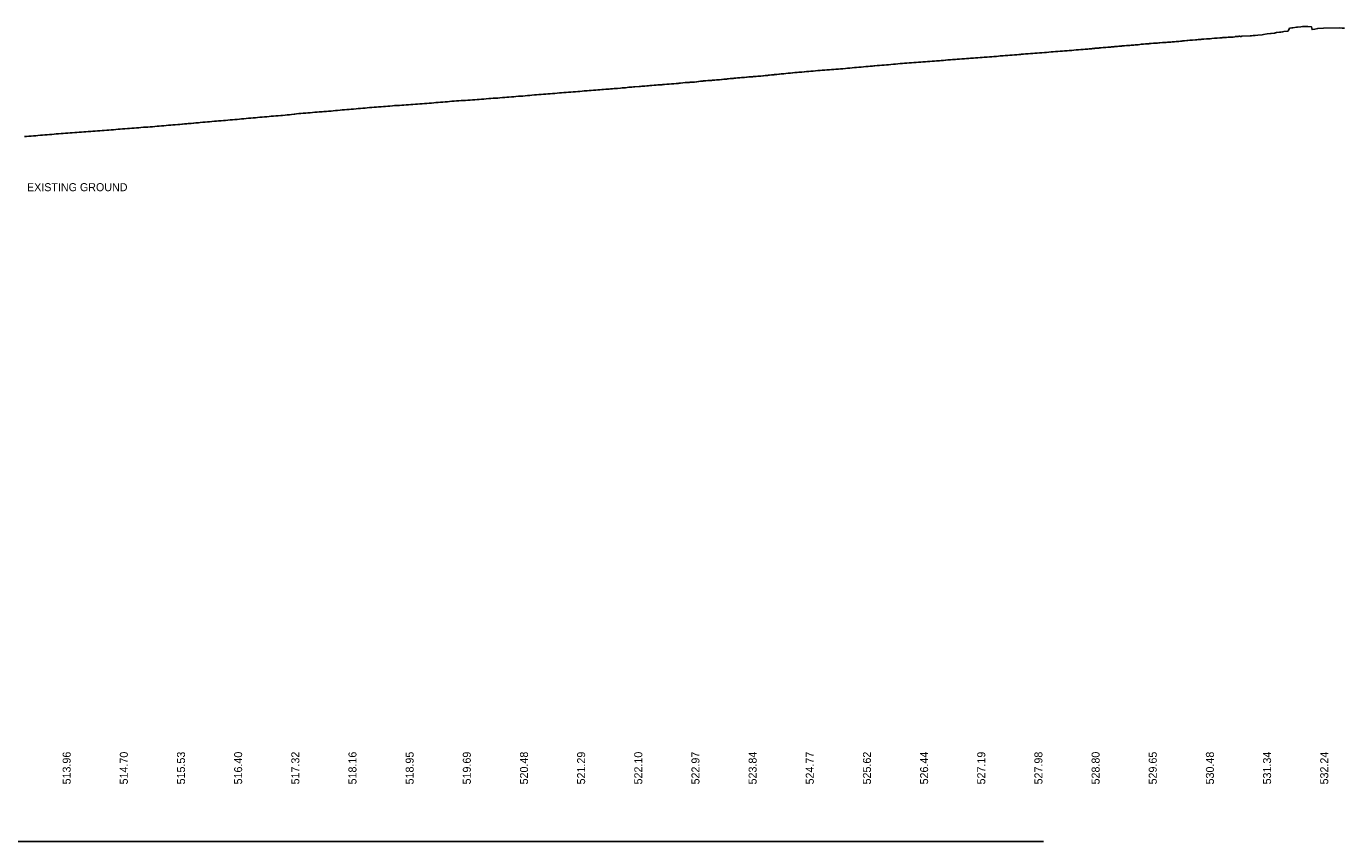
# Model space of a CAD drawing. Extents: x 2017200 to 2047700, y 854850 to 893350.
# Drawn here: x 2021610 to 2022763, y 886100 to 886813 of the extents above; entities that cross this region are included whole.
import ezdxf

# ---------------------------------------------------------------- set-up
doc = ezdxf.new("R2010")
doc.units = 0
for name, color, linetype in [('RD_DDB_Profile_EX', 7, 'Continuous'), ('RD_DDB_Profile_Lbl', 7, 'Continuous'), ('RD_DDB_StripGrade', 7, 'Continuous'), ('RD_GPK_Profile_Cell', 7, 'Continuous')]:
    doc.layers.add(name, color=color, linetype=linetype)

msp = doc.modelspace()

# ---------------------------------------------------------------- linework, layer by layer
at = {"layer": 'RD_DDB_Profile_EX'}
msp.add_lwpolyline([(2021608.5, 886716.4), (2021610.4, 886716.6), (2021612.5, 886716.7), (2021614.5, 886716.9), (2021616.4, 886717), (2021618.5, 886717.2), (2021620.4, 886717.4), (2021622.5, 886717.6), (2021624.5, 886717.7), (2021626.5, 886717.9), (2021628.5, 886718.1), (2021630.5, 886718.3), (2021632.4, 886718.4), (2021634.5, 886718.6), (2021636.4, 886718.7), (2021638.5, 886718.9), (2021640.6, 886719), (2021642.4, 886719.2), (2021644.5, 886719.4), (2021646.5, 886719.5), (2021648.5, 886719.7), (2021650.4, 886719.8), (2021652.5, 886720), (2021654.5, 886720.1), (2021656.4, 886720.2), (2021658.4, 886720.4), (2021660.4, 886720.6), (2021662.4, 886720.7), (2021664.4, 886720.8), (2021666.5, 886720.9), (2021668.4, 886721.1), (2021670.5, 886721.2), (2021672.4, 886721.4), (2021674.5, 886721.5), (2021676.5, 886721.7), (2021678.4, 886721.8), (2021680.5, 886722), (2021682.5, 886722), (2021684.5, 886722.2), (2021686.5, 886722.4), (2021688.5, 886722.5), (2021690.4, 886722.8), (2021692.4, 886722.9), (2021694.4, 886723.1), (2021696.5, 886723.2), (2021698.6, 886723.4), (2021700.5, 886723.6), (2021702.6, 886723.8), (2021704.4, 886723.9), (2021706.5, 886724.1), (2021708.5, 886724.2), (2021710.5, 886724.4), (2021712.7, 886724.6), (2021714.4, 886724.7), (2021716.4, 886724.8), (2021718.5, 886725), (2021720.7, 886725.1), (2021722.5, 886725.3), (2021724.6, 886725.5), (2021726.4, 886725.6), (2021728.5, 886725.8), (2021730.5, 886725.9), (2021732.5, 886726.1), (2021734.5, 886726.3), (2021734.8, 886726.3), (2021736.6, 886726.5), (2021738.4, 886726.7), (2021738.7, 886726.7), (2021740.5, 886726.8), (2021742.7, 886727), (2021744.1, 886727.1), (2021744.5, 886727.1), (2021746.3, 886727.3), (2021746.7, 886727.3), (2021748.5, 886727.5), (2021749.1, 886727.5), (2021750.5, 886727.7), (2021751.9, 886727.8), (2021752.4, 886727.8), (2021754.2, 886728), (2021754.5, 886728), (2021756.5, 886728.2), (2021756.8, 886728.2), (2021758.5, 886728.4), (2021760.3, 886728.5), (2021760.7, 886728.6), (2021762.4, 886728.7), (2021764.6, 886728.9), (2021766.1, 886729), (2021766.5, 886729.1), (2021768.6, 886729.3), (2021770.5, 886729.4), (2021772.5, 886729.6), (2021774.7, 886729.8), (2021776.5, 886730), (2021778.4, 886730.1), (2021780.5, 886730.3), (2021782.6, 886730.5), (2021784.5, 886730.6), (2021786.6, 886730.8), (2021788.4, 886731), (2021790.5, 886731.2), (2021792.5, 886731.3), (2021794.5, 886731.5), (2021796.7, 886731.7), (2021798.4, 886731.9), (2021800.6, 886732), (2021802.5, 886732.2), (2021804.5, 886732.4), (2021806.5, 886732.5), (2021808.5, 886732.7), (2021810.6, 886732.9), (2021812.5, 886733.1), (2021814.4, 886733.3), (2021816.5, 886733.4), (2021818.6, 886733.6), (2021820.5, 886733.7), (2021822.6, 886734), (2021824.4, 886734.2), (2021826.5, 886734.4), (2021828.5, 886734.5), (2021830.5, 886734.7), (2021832.7, 886734.9), (2021834.4, 886735), (2021836.5, 886735.2), (2021838.4, 886735.5), (2021840.3, 886735.6), (2021842.3, 886735.8), (2021844.5, 886736), (2021845.1, 886736.1), (2021846.4, 886736.3), (2021848.5, 886736.5), (2021850.4, 886736.6), (2021852.5, 886736.8), (2021854.6, 886737), (2021856.5, 886737.2), (2021858.6, 886737.3), (2021860.4, 886737.5), (2021862.5, 886737.7), (2021864.5, 886737.9), (2021866.5, 886738), (2021868.5, 886738.1), (2021868.9, 886738.2), (2021870.4, 886738.3), (2021871.9, 886738.4), (2021872.4, 886738.4), (2021872.8, 886738.5), (2021874.5, 886738.6), (2021876.4, 886738.7), (2021876.8, 886738.8), (2021878.5, 886738.9), (2021880.6, 886739.2), (2021882.5, 886739.3), (2021884.6, 886739.6), (2021886.4, 886739.7), (2021888.6, 886739.9), (2021890.5, 886740), (2021892.6, 886740.2), (2021894.4, 886740.3), (2021894.7, 886740.3), (2021896.4, 886740.5), (2021898.6, 886740.7), (2021900.5, 886740.9), (2021902.5, 886741.1), (2021904.5, 886741.2), (2021906.5, 886741.4), (2021908.4, 886741.6), (2021910.5, 886741.8), (2021912.4, 886741.9), (2021914.5, 886742.1), (2021916.5, 886742.2), (2021918.4, 886742.4), (2021919.7, 886742.4), (2021920.5, 886742.5), (2021922.5, 886742.6), (2021924.4, 886742.8), (2021926.5, 886743), (2021928.3, 886743.1), (2021930.5, 886743.3), (2021932.4, 886743.5), (2021934.4, 886743.5), (2021936.5, 886743.7), (2021938.6, 886743.9), (2021940.5, 886744), (2021942.6, 886744.2), (2021944.4, 886744.3), (2021946.5, 886744.5), (2021948.4, 886744.6), (2021950.5, 886744.8), (2021952.5, 886744.9), (2021954.5, 886745), (2021956.5, 886745.2), (2021958.4, 886745.4), (2021960.5, 886745.5), (2021962.5, 886745.6), (2021964.5, 886745.8), (2021966.7, 886746), (2021968.5, 886746.1), (2021970.4, 886746.2), (2021972.5, 886746.4), (2021974.6, 886746.6), (2021976.5, 886746.7), (2021978.5, 886746.9), (2021980.4, 886747), (2021982.5, 886747.3), (2021984.5, 886747.4), (2021986.5, 886747.6), (2021988.5, 886747.7), (2021990.5, 886747.9), (2021992.6, 886748), (2021994.5, 886748.1), (2021996.4, 886748.3), (2021998.5, 886748.4), (2022000.5, 886748.5), (2022002.5, 886748.6), (2022004.5, 886748.8), (2022006.4, 886748.9), (2022008.5, 886749.1), (2022010.5, 886749.2), (2022012.5, 886749.4), (2022014.7, 886749.6), (2022016.4, 886749.7), (2022018.6, 886749.9), (2022020.5, 886750), (2022022.6, 886750.1), (2022024.5, 886750.3), (2022026.6, 886750.5), (2022028.4, 886750.6), (2022028.7, 886750.7), (2022030.5, 886750.8), (2022032.4, 886751), (2022034.5, 886751.1), (2022036.6, 886751.3), (2022038.5, 886751.5), (2022040.6, 886751.7), (2022042.4, 886751.8), (2022044.5, 886751.9), (2022046.5, 886752.1), (2022048.5, 886752.3), (2022050.7, 886752.5), (2022052.4, 886752.6), (2022054.6, 886752.8), (2022056.5, 886752.9), (2022058.5, 886753.1), (2022060.5, 886753.2), (2022062.5, 886753.4), (2022064.5, 886753.6), (2022066.5, 886753.8), (2022068.4, 886753.9), (2022070.5, 886754.1), (2022072.6, 886754.2), (2022074.5, 886754.4), (2022076.6, 886754.6), (2022078.4, 886754.7), (2022080.5, 886754.9), (2022082.5, 886755), (2022084.5, 886755.2), (2022086.6, 886755.4), (2022088.4, 886755.6), (2022090.5, 886755.7), (2022092.5, 886755.9), (2022093.6, 886755.9), (2022094.4, 886756), (2022096.4, 886756.1), (2022098.2, 886756.3), (2022098.8, 886756.3), (2022100.7, 886756.5), (2022102.6, 886756.7), (2022104.4, 886756.8), (2022106.2, 886757), (2022106.7, 886757), (2022108.5, 886757.1), (2022110.2, 886757.2), (2022111.9, 886757.4), (2022113.5, 886757.5), (2022115.2, 886757.6), (2022117, 886757.8), (2022118.6, 886757.9), (2022120.1, 886758), (2022121.3, 886758.1), (2022122.9, 886758.3), (2022124.3, 886758.4), (2022125.8, 886758.5), (2022127.2, 886758.6), (2022129.9, 886758.9), (2022131.4, 886759), (2022132.9, 886759.1), (2022134.3, 886759.2), (2022135.7, 886759.3), (2022137.2, 886759.5), (2022138.6, 886759.6), (2022139.9, 886759.7), (2022141.2, 886759.8), (2022142.6, 886759.8), (2022146.2, 886760.1), (2022147.4, 886760.2), (2022148.6, 886760.4), (2022149.9, 886760.5), (2022151.2, 886760.6), (2022153, 886760.7), (2022154.3, 886760.8), (2022155.7, 886761), (2022157.4, 886761.1), (2022159.3, 886761.3), (2022161.2, 886761.4), (2022162.7, 886761.6), (2022164.4, 886761.7), (2022166.3, 886761.8), (2022166.6, 886761.9), (2022168.5, 886762), (2022170.5, 886762.2), (2022172.5, 886762.3), (2022174.5, 886762.5), (2022176.5, 886762.6), (2022178.5, 886762.8), (2022180.5, 886762.9), (2022181.2, 886763), (2022182.5, 886763.2), (2022184.6, 886763.4), (2022186.5, 886763.6), (2022188.1, 886763.7), (2022188.4, 886763.7), (2022190.2, 886763.8), (2022190.5, 886763.9), (2022192.5, 886764), (2022192.9, 886764), (2022193.9, 886764.1), (2022194.6, 886764.1), (2022196.3, 886764.3), (2022196.8, 886764.4), (2022198.4, 886764.7), (2022200, 886764.8), (2022200.7, 886764.9), (2022201.9, 886765), (2022202.5, 886765.1), (2022204.2, 886765.2), (2022204.7, 886765.3), (2022206.2, 886765.4), (2022206.5, 886765.4), (2022207.2, 886765.5), (2022208.4, 886765.6), (2022209.5, 886765.6), (2022210.4, 886765.7), (2022211.1, 886765.8), (2022212.5, 886765.9), (2022214, 886766), (2022214.4, 886766.1), (2022214.9, 886766.1), (2022216, 886766.2), (2022216.6, 886766.2), (2022218.2, 886766.4), (2022218.9, 886766.4), (2022220.3, 886766.5), (2022221.7, 886766.6), (2022222.6, 886766.7), (2022223.5, 886766.8), (2022224.4, 886766.9), (2022226, 886767.1), (2022226.7, 886767.1), (2022228, 886767.3), (2022228.5, 886767.3), (2022229.3, 886767.4), (2022230.2, 886767.5), (2022230.7, 886767.5), (2022232.3, 886767.7), (2022233.1, 886767.8), (2022234.4, 886767.9), (2022235.8, 886768), (2022236.4, 886768.1), (2022236.8, 886768.1), (2022237.7, 886768.2), (2022238.5, 886768.2), (2022240.1, 886768.4), (2022240.8, 886768.4), (2022242.2, 886768.6), (2022242.6, 886768.6), (2022243.6, 886768.7), (2022244.4, 886768.7), (2022245.3, 886768.8), (2022246.4, 886768.9), (2022247.2, 886769), (2022248.5, 886769.1), (2022250, 886769.2), (2022250.4, 886769.2), (2022251.1, 886769.3), (2022252, 886769.4), (2022252.6, 886769.4), (2022254.5, 886769.6), (2022254.9, 886769.6), (2022256.6, 886769.8), (2022258.6, 886769.9), (2022259.5, 886770), (2022260.4, 886770.1), (2022262.1, 886770.3), (2022262.7, 886770.3), (2022264.1, 886770.5), (2022264.5, 886770.6), (2022266.2, 886770.8), (2022266.7, 886770.8), (2022268.5, 886771), (2022268.9, 886771.1), (2022270.4, 886771.2), (2022272, 886771.3), (2022272.4, 886771.4), (2022272.8, 886771.4), (2022274.5, 886771.6), (2022276.7, 886771.8), (2022278.2, 886772), (2022278.5, 886772), (2022280.3, 886772.1), (2022280.7, 886772.2), (2022282.4, 886772.4), (2022283.2, 886772.4), (2022284.6, 886772.6), (2022286, 886772.7), (2022286.5, 886772.7), (2022288.2, 886772.9), (2022288.6, 886772.9), (2022290.5, 886773.1), (2022290.9, 886773.1), (2022292.6, 886773.2), (2022294.4, 886773.4), (2022294.7, 886773.4), (2022296.5, 886773.6), (2022298.6, 886773.7), (2022300.5, 886773.9), (2022302.5, 886774.1), (2022304.6, 886774.2), (2022306.4, 886774.4), (2022308.7, 886774.5), (2022310.5, 886774.7), (2022312.7, 886774.9), (2022314.5, 886775), (2022316.6, 886775.2), (2022318.4, 886775.3), (2022320.5, 886775.5), (2022322.5, 886775.7), (2022324.5, 886775.8), (2022326.7, 886776), (2022328.5, 886776.2), (2022330.6, 886776.4), (2022332.5, 886776.5), (2022334.6, 886776.7), (2022336.5, 886776.9), (2022338.5, 886777.1), (2022340.5, 886777.2), (2022342.5, 886777.4), (2022344.4, 886777.6), (2022346.5, 886777.8), (2022348.4, 886778), (2022350.4, 886778.1), (2022351.5, 886778.2), (2022352.4, 886778.3), (2022354.5, 886778.5), (2022356.5, 886778.7), (2022358.4, 886778.8), (2022360.7, 886779), (2022362.5, 886779.2), (2022364.5, 886779.3), (2022366.5, 886779.5), (2022368.6, 886779.7), (2022370.5, 886779.9), (2022372.4, 886780), (2022374.5, 886780.2), (2022376.5, 886780.3), (2022378.5, 886780.5), (2022380.5, 886780.7), (2022382.5, 886780.8), (2022384.4, 886781), (2022386.5, 886781.1), (2022388.5, 886781.3), (2022390.5, 886781.5), (2022392.6, 886781.6), (2022394.4, 886781.8), (2022394.8, 886781.8), (2022396.7, 886781.9), (2022398.5, 886782.1), (2022400.2, 886782.2), (2022400.5, 886782.2), (2022402.6, 886782.4), (2022404, 886782.5), (2022404.7, 886782.5), (2022406.3, 886782.7), (2022406.7, 886782.7), (2022408.5, 886782.8), (2022408.9, 886782.8), (2022410.4, 886782.9), (2022411.8, 886783), (2022412.5, 886783.1), (2022414.2, 886783.3), (2022414.6, 886783.3), (2022416.4, 886783.4), (2022416.7, 886783.5), (2022418.7, 886783.6), (2022420.4, 886783.7), (2022422.1, 886783.8), (2022422.5, 886783.9), (2022423, 886783.9), (2022424.5, 886784), (2022426, 886784.1), (2022426.6, 886784.1), (2022428.6, 886784.3), (2022430.4, 886784.5), (2022430.8, 886784.5), (2022432.7, 886784.6), (2022434.5, 886784.8), (2022436.2, 886784.9), (2022436.5, 886784.9), (2022438.6, 886785.1), (2022440.6, 886785.2), (2022442.6, 886785.4), (2022444.5, 886785.5), (2022444.8, 886785.6), (2022446.4, 886785.7), (2022448, 886785.8), (2022448.5, 886785.9), (2022450.6, 886786), (2022452.7, 886786.2), (2022454.7, 886786.3), (2022456.4, 886786.5), (2022458.2, 886786.6), (2022458.5, 886786.6), (2022458.9, 886786.6), (2022460.5, 886786.8), (2022462.1, 886786.9), (2022462.6, 886786.9), (2022464.3, 886787.1), (2022464.6, 886787.1), (2022466.4, 886787.2), (2022466.8, 886787.3), (2022468.3, 886787.4), (2022468.8, 886787.4), (2022470.5, 886787.5), (2022472.2, 886787.7), (2022472.6, 886787.7), (2022474.6, 886787.9), (2022476.7, 886788), (2022478.4, 886788.2), (2022479, 886788.3), (2022480, 886788.3), (2022480.5, 886788.4), (2022480.9, 886788.4), (2022482.4, 886788.6), (2022484.1, 886788.7), (2022484.5, 886788.7), (2022486.6, 886788.9), (2022488.6, 886789), (2022490.6, 886789.2), (2022492.4, 886789.3), (2022494.5, 886789.5), (2022496.5, 886789.6), (2022498.5, 886789.8), (2022500.7, 886790), (2022502.1, 886790.1), (2022502.7, 886790.1), (2022504.6, 886790.3), (2022506.5, 886790.4), (2022506.9, 886790.4), (2022508.4, 886790.6), (2022510.5, 886790.7), (2022512.5, 886790.9), (2022514.4, 886791), (2022516.5, 886791.2), (2022518.4, 886791.4), (2022520.5, 886791.5), (2022522.5, 886791.7), (2022524.5, 886791.8), (2022524.8, 886791.8), (2022526.4, 886792), (2022528.5, 886792.2), (2022530.6, 886792.4), (2022532.5, 886792.5), (2022534.6, 886792.7), (2022536.4, 886792.8), (2022538.6, 886793), (2022540, 886793.1), (2022540.5, 886793.2), (2022542.2, 886793.3), (2022542.6, 886793.4), (2022544.5, 886793.5), (2022545, 886793.6), (2022546.6, 886793.7), (2022548.4, 886793.8), (2022548.9, 886793.9), (2022550.5, 886794), (2022552.1, 886794.2), (2022552.4, 886794.2), (2022552.8, 886794.2), (2022554, 886794.4), (2022554.5, 886794.4), (2022556.2, 886794.5), (2022556.8, 886794.6), (2022558.3, 886794.7), (2022558.6, 886794.7), (2022559.4, 886794.8), (2022560.5, 886794.9), (2022561.5, 886795), (2022562.4, 886795.1), (2022563.9, 886795.2), (2022564.6, 886795.3), (2022565.9, 886795.4), (2022566.5, 886795.4), (2022567.2, 886795.5), (2022568.1, 886795.6), (2022568.7, 886795.7), (2022570.8, 886795.8), (2022572.4, 886796), (2022573.5, 886796.1), (2022574.8, 886796.2), (2022575.5, 886796.2), (2022576.5, 886796.3), (2022578, 886796.4), (2022578.9, 886796.5), (2022580, 886796.6), (2022581.7, 886796.7), (2022582.3, 886796.8), (2022582.8, 886796.8), (2022584.2, 886797), (2022585.3, 886797.1), (2022586.6, 886797.2), (2022587.5, 886797.2), (2022589.2, 886797.4), (2022589.6, 886797.4), (2022590.7, 886797.5), (2022592, 886797.6), (2022592.6, 886797.7), (2022594.1, 886797.8), (2022596.2, 886798), (2022596.6, 886798), (2022596.9, 886798), (2022598, 886798.1), (2022599.5, 886798.2), (2022599.8, 886798.2), (2022600.8, 886798.3), (2022601.6, 886798.4), (2022603.9, 886798.6), (2022605.1, 886798.7), (2022606.4, 886798.8), (2022607.1, 886798.8), (2022608.3, 886798.9), (2022608.8, 886799), (2022611.2, 886799.1), (2022612.5, 886799.2), (2022613.6, 886799.3), (2022613.9, 886799.3), (2022614.4, 886799.4), (2022616, 886799.5), (2022616.8, 886799.6), (2022618.4, 886799.7), (2022619.7, 886799.9), (2022620.8, 886800), (2022621.1, 886800), (2022621.6, 886800.1), (2022623.2, 886800.2), (2022625.3, 886800.4), (2022625.6, 886800.4), (2022626.2, 886800.5), (2022628, 886800.6), (2022628.9, 886800.7), (2022630.4, 886800.8), (2022632.8, 886801), (2022634.1, 886801.1), (2022635.2, 886801.2), (2022635.6, 886801.2), (2022636.2, 886801.3), (2022637, 886801.3), (2022637.6, 886801.4), (2022638.4, 886801.5), (2022640, 886801.6), (2022640.3, 886801.6), (2022642.4, 886801.8), (2022643.4, 886801.9), (2022644.7, 886801.9), (2022645.7, 886802), (2022647.3, 886802.2), (2022649.5, 886802.4), (2022650.7, 886802.5), (2022651.9, 886802.6), (2022654.3, 886802.8), (2022655.8, 886802.9), (2022656.7, 886803), (2022658, 886803.1), (2022658.7, 886803.2), (2022659.1, 886803.2), (2022659.9, 886803.1), (2022661.5, 886803.4), (2022662.7, 886803.4), (2022665.9, 886803.5), (2022667.3, 886803.7), (2022667.6, 886803.8), (2022668.8, 886804), (2022670.1, 886803.9), (2022671.1, 886804.2), (2022671.5, 886804.1), (2022672.2, 886804), (2022672.9, 886804), (2022673.5, 886804.1), (2022680.7, 886804.5), (2022681.9, 886804.6), (2022683.4, 886804.7), (2022685.1, 886804.9), (2022687.4, 886805.1), (2022691.1, 886805.5), (2022692.5, 886805.7), (2022695.7, 886806.2), (2022698.5, 886806.5), (2022699.2, 886806.6), (2022702.1, 886807), (2022703.7, 886807.3), (2022706.4, 886807.7), (2022707.4, 886807.8), (2022709.1, 886808), (2022710.2, 886808.2), (2022713.8, 886808.7), (2022714.4, 886809.7), (2022715.2, 886811.2), (2022717.1, 886811.4), (2022718.1, 886811.6), (2022721.3, 886812.1), (2022721.6, 886812.2), (2022722.1, 886812.2), (2022724.9, 886812.5), (2022726.4, 886812.7), (2022728, 886812.8), (2022730.8, 886812.7), (2022731.2, 886812.6), (2022734.3, 886812.5), (2022734.9, 886810), (2022737.3, 886810.4), (2022739.8, 886811), (2022744.8, 886811.1), (2022759.1, 886811.5), (2022761.1, 886811.3), (2022763.3, 886811.1)], dxfattribs=at)
at = {"layer": 'RD_GPK_Profile_Cell'}
msp.add_line((2020500, 886100), (2022500, 886100), dxfattribs=at)

# ---------------------------------------------------------------- texts
at = {"layer": 'RD_DDB_Profile_Lbl'}
msp.add_text('EXISTING GROUND', height=7, dxfattribs=at).set_placement((2021610.8, 886668.7))
at = {"layer": 'RD_DDB_StripGrade'}
for s, p in [('513.96', (2021649, 886150)), ('514.70', (2021699, 886150)), ('515.53', (2021749, 886150)), ('516.40', (2021799, 886150)), ('517.32', (2021849, 886150)), ('518.16', (2021899, 886150)), ('518.95', (2021949, 886150)), ('519.69', (2021999, 886150)), ('520.48', (2022049, 886150)), ('521.29', (2022099, 886150)), ('522.10', (2022149, 886150)), ('522.97', (2022199, 886150)), ('523.84', (2022249, 886150)), ('524.77', (2022299, 886150)), ('525.62', (2022349, 886150)), ('526.44', (2022399, 886150)), ('527.19', (2022449, 886150)), ('527.98', (2022499, 886150)), ('528.80', (2022549, 886150)), ('529.65', (2022599, 886150)), ('530.48', (2022649, 886150)), ('531.34', (2022699, 886150)), ('532.24', (2022749, 886150))]:
    msp.add_text(s, height=7, rotation=90, dxfattribs=at).set_placement(p)

doc.saveas('drawing.dxf')
